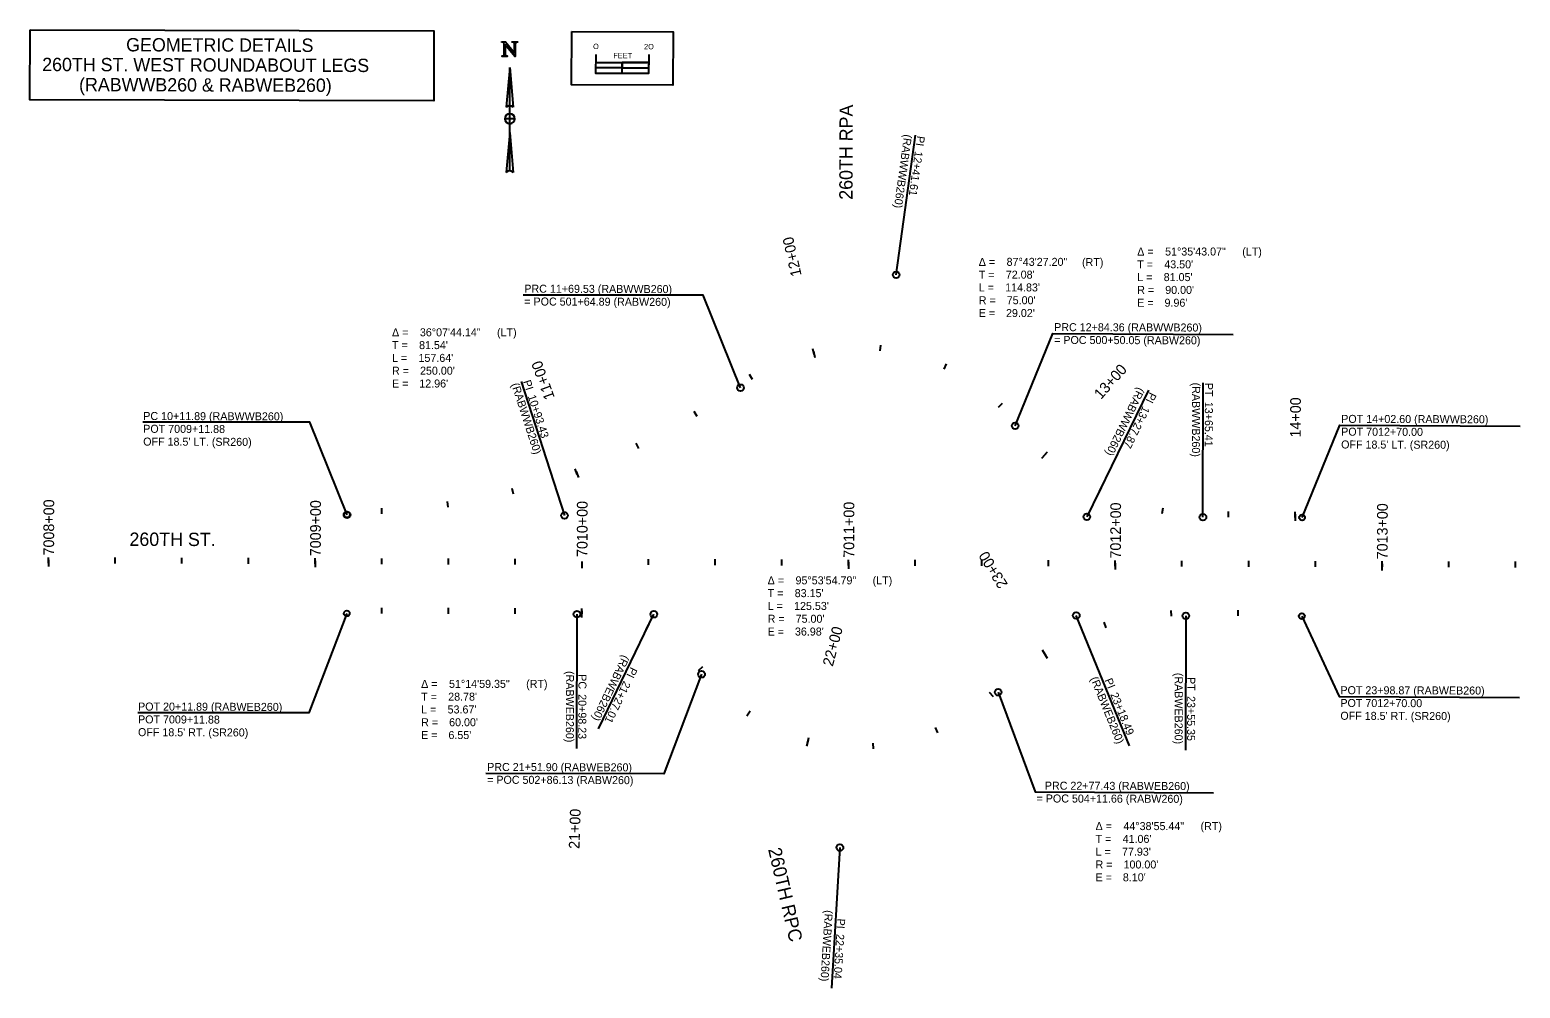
# Model space of a CAD drawing. Extents: x 5195296 to 5198948, y 3709168 to 3709552.
# Drawn here: x 5196591 to 5197150, y 3709193 to 3709552 of the extents above; entities that cross this region are included whole.
import ezdxf

# ---------------------------------------------------------------- set-up
doc = ezdxf.new("R2010")
doc.units = 0
for name, color, linetype in [('dsnAlignmentStation', 7, 'Continuous'), ('dsnGeopakCellProfile', 7, 'Continuous'), ('dsnProfileEntranceGradeProp', 7, 'Continuous')]:
    doc.layers.add(name, color=color, linetype=linetype)

msp = doc.modelspace()

# ---------------------------------------------------------------- linework, layer by layer
at = {"layer": 'dsnAlignmentStation'}
for p, q in [((5196597.84, 3709353.39), (5196597.83, 3709350.94)), ((5196622.84, 3709352.09), (5196622.84, 3709354.28)), ((5196647.84, 3709352.02), (5196647.84, 3709354.21)), ((5196672.84, 3709351.95), (5196672.84, 3709354.13)), ((5196697.84, 3709353.1), (5196697.83, 3709350.65)), ((5196722.84, 3709351.81), (5196722.84, 3709353.99)), ((5196747.84, 3709351.73), (5196747.84, 3709353.92)), ((5196772.84, 3709351.66), (5196772.84, 3709353.84)), ((5196822.84, 3709351.52), (5196822.84, 3709353.7)), ((5196847.84, 3709351.44), (5196847.84, 3709353.63)), ((5196872.84, 3709351.37), (5196872.84, 3709353.56)), ((5196922.84, 3709351.23), (5196922.84, 3709353.41)), ((5196947.84, 3709351.16), (5196947.84, 3709353.34)), ((5196972.84, 3709351.08), (5196972.84, 3709353.27)), ((5197022.84, 3709350.94), (5197022.84, 3709353.12)), ((5197047.84, 3709350.87), (5197047.84, 3709353.05)), ((5197072.84, 3709350.79), (5197072.84, 3709352.98)), ((5197122.84, 3709350.65), (5197122.84, 3709352.83)), ((5196797.84, 3709352.81), (5196797.83, 3709350.36)), ((5196897.84, 3709352.52), (5196897.83, 3709350.08)), ((5196997.84, 3709352.23), (5196997.83, 3709349.79)), ((5197097.84, 3709351.95), (5197097.83, 3709349.5)), ((5197147.84, 3709350.58), (5197147.84, 3709352.76))]:
    msp.add_line(p, q, dxfattribs=at)
at = {"layer": 'dsnGeopakCellProfile'}
for p, q in [((5196770.8, 3709538.11), (5196769.49, 3709523.16)), ((5196770.8, 3709538.11), (5196772.11, 3709523.16)), ((5196770.8, 3709523.73), (5196770.8, 3709538.11)), ((5196770.8, 3709499.27), (5196770.8, 3709538.11)), ((5196812.99, 3709535.93), (5196813, 3709539.93)), ((5196812.99, 3709535.93), (5196813, 3709539.93)), ((5196770.8, 3709523.7), (5196770.8, 3709523.73)), ((5196770.8, 3709518.86), (5196770.8, 3709520.73)), ((5196770.8, 3709518.86), (5196768.93, 3709518.86)), ((5196772.68, 3709518.86), (5196768.93, 3709518.86)), ((5196772.68, 3709518.86), (5196770.8, 3709518.86)), ((5196770.8, 3709516.98), (5196770.8, 3709518.86)), ((5196770.8, 3709513.68), (5196769.49, 3709498.74)), ((5196770.8, 3709499.27), (5196770.8, 3709513.68)), ((5196770.8, 3709513.68), (5196772.11, 3709498.74)), ((5196915.65, 3709460.32), (5196922.91, 3709512.62)), ((5196922.91, 3709512.62), (5196922.91, 3709512.62)), ((5196884.89, 3709430.46), (5196884.41, 3709432.59)), ((5196884.62, 3709431.65), (5196885.15, 3709429.26)), ((5196909.73, 3709431.82), (5196909.98, 3709433.99)), ((5196933.66, 3709424.98), (5196934.6, 3709426.95)), ((5196775.09, 3709420.35), (5196791.31, 3709370.11)), ((5196861.85, 3709421.04), (5196860.7, 3709422.9)), ((5197010.31, 3709417.01), (5196987.19, 3709369.54)), ((5197030.7, 3709369.42), (5197030.84, 3709419.82)), ((5197030.84, 3709419.82), (5197030.84, 3709419.82)), ((5196841.07, 3709407.15), (5196839.93, 3709409.01)), ((5196954.03, 3709410.68), (5196955.56, 3709412.24)), ((5196819.14, 3709395.18), (5196818.19, 3709397.15)), ((5196971.78, 3709393.24), (5196970.14, 3709391.42)), ((5196970.96, 3709392.33), (5196972.42, 3709393.96)), ((5196796.12, 3709385.46), (5196795.37, 3709387.51)), ((5196795.7, 3709386.61), (5196796.53, 3709384.31)), ((5196747.74, 3709373.13), (5196747.42, 3709375.29)), ((5196772.24, 3709378.09), (5196771.7, 3709380.2)), ((5196991.66, 3709378.45), (5196992.61, 3709380.41)), ((5196722.88, 3709370.65), (5196722.77, 3709372.83)), ((5197015.37, 3709370.78), (5197015.74, 3709372.93)), ((5197040.29, 3709369.39), (5197040.29, 3709371.57)), ((5197065.29, 3709370.54), (5197065.28, 3709368.09)), ((5197065.29, 3709369.32), (5197065.29, 3709371.5)), ((5196722.78, 3709333.31), (5196722.78, 3709335.49)), ((5196747.78, 3709333.23), (5196747.78, 3709335.42)), ((5196772.78, 3709333.16), (5196772.78, 3709335.35)), ((5196796, 3709333.09), (5196795.86, 3709282.69)), ((5196797.82, 3709334.29), (5196797.74, 3709331.84)), ((5196797.78, 3709333.06), (5196797.85, 3709335.25)), ((5196804.03, 3709290.06), (5196824.78, 3709333.01)), ((5197003.12, 3709283.65), (5196983.21, 3709332.55)), ((5196983.21, 3709332.55), (5196983.21, 3709332.55)), ((5197018.92, 3709332.31), (5197018.81, 3709334.49)), ((5197024.27, 3709332.43), (5197024.12, 3709282.03)), ((5197043.92, 3709332.38), (5197043.92, 3709334.56)), ((5196821.88, 3709327.14), (5196822.83, 3709329.11)), ((5196994.37, 3709327.95), (5196993.72, 3709330.04)), ((5196971.66, 3709317.65), (5196970.51, 3709319.51)), ((5196971.02, 3709318.7), (5196972.3, 3709316.61)), ((5196841.53, 3709311.98), (5196843.19, 3709313.39)), ((5196952.15, 3709302.11), (5196950.67, 3709303.72)), ((5196859.67, 3709294.94), (5196860.89, 3709296.76)), ((5196882.68, 3709285.92), (5196882.06, 3709283.55)), ((5196882.37, 3709284.73), (5196882.92, 3709286.85)), ((5196931.3, 3709288.53), (5196930.43, 3709290.53)), ((5196795.86, 3709282.69), (5196795.86, 3709282.69)), ((5196907.15, 3709282.51), (5196906.99, 3709284.69)), ((5196989.23, 3709267.82), (5196989.23, 3709267.82)), ((5196894.59, 3709245.52), (5196891.4, 3709192.82)), ((5196891.4, 3709192.82), (5196891.4, 3709192.82))]:
    msp.add_line(p, q, dxfattribs=at)
for points in [[(5196590.92, 3709552.19), (5196742.34, 3709551.75), (5196742.27, 3709525.5), (5196590.84, 3709525.93)], [(5196590.92, 3709552.19), (5196742.34, 3709551.75), (5196742.27, 3709525.5), (5196590.84, 3709525.93)], [(5196794.03, 3709551.58), (5196832.03, 3709551.47), (5196831.98, 3709531.47), (5196793.98, 3709531.58)], [(5196794.03, 3709551.58), (5196832.03, 3709551.47), (5196831.98, 3709531.47), (5196793.98, 3709531.58)], [(5196802.99, 3709535.95), (5196812.99, 3709535.93), (5196812.99, 3709537.94), (5196802.99, 3709537.97)], [(5196812.99, 3709537.94), (5196822.99, 3709537.91), (5196823, 3709539.9), (5196813, 3709539.93)]]:
    msp.add_lwpolyline(points, close=True, dxfattribs=at)
for points in [[(5196767.67, 3709547.72), (5196769.15, 3709547.72), (5196772.52, 3709543.59), (5196772.52, 3709546.77)], [(5196767.67, 3709547.57), (5196767.67, 3709547.72)], [(5196768.75, 3709543.17), (5196768.75, 3709547)], [(5196772.87, 3709546.77), (5196772.87, 3709542.13), (5196772.73, 3709542.13), (5196769.11, 3709546.56), (5196769.11, 3709543.17)], [(5196771.93, 3709547.57), (5196771.74, 3709547.57), (5196771.74, 3709547.72), (5196773.65, 3709547.72), (5196773.65, 3709547.57), (5196773.46, 3709547.57)], [(5196803.01, 3709542.95), (5196802.99, 3709535.95), (5196822.99, 3709535.9), (5196823.01, 3709542.9)], [(5196769.69, 3709542.37), (5196769.88, 3709542.37), (5196769.88, 3709542.22), (5196767.97, 3709542.22), (5196767.97, 3709542.37), (5196768.16, 3709542.37)], [(5196803, 3709539.95), (5196823, 3709539.9)], [(5196857.31, 3709417.99), (5196843.36, 3709452.68), (5196775.76, 3709452.74)], [(5196960.27, 3709403.71), (5196974.42, 3709438.32), (5197042.02, 3709437.98)], [(5196709.77, 3709370.34), (5196695.82, 3709405.03), (5196633.18, 3709405.08)], [(5197067.89, 3709369.31), (5197082.04, 3709403.92), (5197149.64, 3709403.58)], [(5196709.67, 3709333.34), (5196695.51, 3709296.08), (5196631.32, 3709296.13)], [(5197067.78, 3709332.31), (5197081.75, 3709302.18), (5197149.35, 3709301.85)], [(5196842.73, 3709310.51), (5196828.57, 3709273.25), (5196761.8, 3709273.3)], [(5196953.91, 3709303.78), (5196967.85, 3709266.44), (5197034.62, 3709266.1)]]:
    msp.add_lwpolyline(points, dxfattribs=at)
for centre, radius in [((5196915.65, 3709460.32), 1.25), ((5196857.31, 3709417.99), 1.25), ((5196857.31, 3709417.99), 1.25), ((5196960.27, 3709403.71), 1.25), ((5196960.27, 3709403.71), 1.25), ((5196709.77, 3709370.34), 1.25), ((5196709.77, 3709370.34), 1.07), ((5196791.31, 3709370.11), 1.25), ((5196987.19, 3709369.54), 1.25), ((5197030.7, 3709369.42), 1.25), ((5197067.89, 3709369.31), 1.07), ((5196709.67, 3709333.34), 1.07), ((5196796, 3709333.09), 1.25), ((5196824.78, 3709333.01), 1.25), ((5196983.21, 3709332.55), 1.25), ((5197024.27, 3709332.43), 1.25), ((5197067.78, 3709332.31), 1.07), ((5196842.73, 3709310.51), 1.25), ((5196842.73, 3709310.51), 1.25), ((5196953.91, 3709303.78), 1.25), ((5196953.91, 3709303.78), 1.25), ((5196894.59, 3709245.52), 1.25)]:
    msp.add_circle(centre, radius, dxfattribs=at)
for centre, start, end in [((5196770.8, 3709518.86), 90, 89.4464), ((5196770.8, 3709521.82), 45.7867, 134.2133), ((5196770.8, 3709521.82), 90, 134.2134), ((5196770.8, 3709518.86), 360, 89.9989), ((5196770.8, 3709518.86), 180, 270), ((5196770.8, 3709497.39), 45.7867, 134.2134), ((5196770.8, 3709497.39), 45.7867, 90)]:
    msp.add_arc(centre, 1.87, start, end, dxfattribs=at)
for points in [[(5196768.75, 3709547), (5196768.51, 3709547.28), (5196768.39, 3709547.37), (5196768.26, 3709547.46), (5196768.02, 3709547.54), (5196767.91, 3709547.57), (5196767.67, 3709547.57)], [(5196768.16, 3709542.37), (5196768.52, 3709542.37), (5196768.66, 3709542.58), (5196768.75, 3709542.71), (5196768.75, 3709543.17)], [(5196769.11, 3709543.17), (5196769.11, 3709542.67), (5196769.21, 3709542.54), (5196769.37, 3709542.37), (5196769.69, 3709542.37)], [(5196772.52, 3709546.77), (5196772.52, 3709547.28), (5196772.41, 3709547.4), (5196772.26, 3709547.57), (5196771.93, 3709547.57)], [(5196773.46, 3709547.57), (5196773.11, 3709547.57), (5196772.96, 3709547.36), (5196772.87, 3709547.23), (5196772.87, 3709546.77)]]:
    msp.add_open_spline(points, degree=3, dxfattribs=at)
at = {"layer": 'dsnProfileEntranceGradeProp'}
for p, q in [((5196597.84, 3709352.17), (5196597.84, 3709354.35)), ((5196697.84, 3709351.88), (5196697.84, 3709354.06)), ((5196897.84, 3709351.3), (5196897.84, 3709353.48)), ((5196997.84, 3709351.01), (5196997.84, 3709353.19)), ((5197097.84, 3709350.72), (5197097.84, 3709352.91)), ((5196797.84, 3709352.81), (5196797.83, 3709350.36))]:
    msp.add_line(p, q, dxfattribs=at)

# ---------------------------------------------------------------- texts
at = {"layer": 'dsnAlignmentStation'}
for s, p in [('7008+00', (5196599.93, 3709355.07)), ('7009+00', (5196699.93, 3709354.78)), ('7010+00', (5196799.93, 3709354.49)), ('7011+00', (5196899.93, 3709354.2)), ('7012+00', (5196999.93, 3709353.92)), ('7013+00', (5197099.93, 3709353.63))]:
    msp.add_text(s, height=4.008, rotation=89.8345, dxfattribs=at).set_placement(p)
at = {"layer": 'dsnGeopakCellProfile'}
for s, height, rotation, p in [('GEOMETRIC DETAILS', 5, 359.8345, (5196626.96, 3709544.1)), ('O', 2, 359.8345, (5196802.03, 3709544.96)), ('FEET', 2, 359.8345, (5196809.62, 3709541.54)), ('2O', 2, 359.8345, (5196821.14, 3709544.9)), ('260TH ST. WEST ROUNDABOUT LEGS', 5, 359.8345, (5196595.47, 3709536.7)), ('(RABWWB260 & RABWEB260)', 5, 359.8345, (5196609.3, 3709529.16)), ('260TH RPA', 5, 89.8345, (5196899.33, 3709488.45)), ('(RABWWB260)', 3, 262.1013, (5196918.66, 3709513.1)), ('PI ', 3, 262.1013, (5196923.51, 3709512.54)), ('12+41.61', 3, 262.1013, (5196922.71, 3709506.8)), ('12+00', 4.008, 102.6877, (5196880.25, 3709460.17)), ('PRC 11+69.53 (RABWWB260)', 3, 359.8345, (5196776.25, 3709453.62)), ('= POC 501+64.89 (RABW260)', 3, 359.8345, (5196776.24, 3709448.82)), ('PRC 12+84.36 (RABWWB260)', 3, 359.8345, (5196974.91, 3709439.2)), ('= POC 500+50.05 (RABW260)', 3, 359.8345, (5196974.9, 3709434.4)), ('11+00', 4.008, 110.0278, (5196787.72, 3709414.33)), ('13+00', 4.008, 48.194, (5196992.45, 3709413.36)), ('PI ', 3, 287.8989, (5196775.74, 3709420.32)), ('(RABWWB260)', 3, 287.8989, (5196771.35, 3709419.26)), ('10+93.43', 3, 287.8989, (5196777.52, 3709414.8)), ('(RABWWB260)', 3, 244.0368, (5197006.29, 3709418.35)), ('PI ', 3, 244.0368, (5197010.74, 3709416.52)), ('(RABWWB260)', 3, 269.8345, (5197026.66, 3709419.9)), ('PT', 3, 269.8345, (5197031.45, 3709419.81)), ('PC 10+11.89 (RABWWB260)', 3, 359.8345, (5196633.38, 3709405.88)), ('13+27.87', 3, 244.0368, (5197008.21, 3709411.31)), ('13+65.41', 3, 269.8345, (5197031.43, 3709412.7)), ('14+00', 4.008, 89.8345, (5197067.38, 3709399.31)), ('POT 7009+11.88 ', 3, 359.8345, (5196633.36, 3709401.08)), ('POT 14+02.60 (RABWWB260)', 3, 359.8345, (5197082.54, 3709404.8)), ("OFF 18.5' LT. (SR260)", 3, 359.8345, (5196633.35, 3709396.28)), ("OFF 18.5' LT. (SR260)", 3, 359.8345, (5197082.51, 3709395.2)), ('POT 7012+70.00', 3, 359.8345, (5197082.52, 3709400)), ('260TH ST.', 5, 359.8345, (5196628.2, 3709358.68)), ('23+00', 4.008, 121.5497, (5196957.67, 3709344.27)), ('22+00', 4.008, 75.3334, (5196891.9, 3709313.25)), ('(RABWEB260)', 3, 244.2095, (5196813.18, 3709317.98)), ('(RABWEB260)', 3, 269.8345, (5196791.89, 3709311.74)), ('PC', 3, 269.8345, (5196796.55, 3709310.55)), ('PI ', 3, 244.2095, (5196816.09, 3709313.48)), ('(RABWEB260)', 3, 292.1588, (5196988.41, 3709308.93)), ('PI ', 3, 292.1588, (5196993.73, 3709308.33)), ('(RABWEB260)', 3, 269.8345, (5197020.16, 3709311.08)), ('PT', 3, 269.8345, (5197024.81, 3709309.49)), ('20+98.23', 3, 269.8345, (5196796.52, 3709303.06)), ('21+27.01', 3, 244.2095, (5196813.56, 3709308.26)), ('23+18.49', 3, 292.1588, (5196995.91, 3709302.96)), ('POT 23+98.87 (RABWEB260)', 3, 359.8345, (5197082.24, 3709303.07)), ('POT 20+11.89 (RABWEB260)', 3, 359.8345, (5196631.43, 3709296.93)), ('23+55.35', 3, 269.8345, (5197024.79, 3709302.37)), ('POT 7012+70.00', 3, 359.8345, (5197082.23, 3709298.27)), ('POT 7009+11.88 ', 3, 359.8345, (5196631.42, 3709292.13)), ("OFF 18.5' RT. (SR260)", 3, 359.8345, (5197082.22, 3709293.47)), ("OFF 18.5' RT. (SR260)", 3, 359.8345, (5196631.41, 3709287.33)), ('PRC 21+51.90 (RABWEB260)', 3, 359.8345, (5196762.33, 3709274.28)), ('= POC 502+86.13 (RABW260)', 3, 359.8345, (5196762.31, 3709269.48)), ('PRC 22+77.43 (RABWEB260)', 3, 359.8345, (5196971.41, 3709267.26)), ('= POC 504+11.66 (RABW260)', 3, 359.8345, (5196968.31, 3709262.47)), ('21+00', 4.008, 88.1416, (5196796.92, 3709244.99)), ('260TH RPC', 5, 283.0965, (5196867.62, 3709244.93)), ('(RABWEB260)', 3, 266.5339, (5196888.92, 3709222.15)), ('PI ', 3, 266.5339, (5196893.59, 3709219)), ('22+35.04', 3, 266.5339, (5196893.24, 3709213.21))]:
    msp.add_text(s, height=height, rotation=rotation, dxfattribs=at).set_placement(p)
for s, p in [('Δ = ', (5197006.06, 3709467.55)), ('51°35\'43.07"', (5197016.51, 3709467.55)), (' (LT)', (5197044.31, 3709467.55)), ('Δ = ', (5196946.64, 3709463.68)), ('87°43\'27.20"', (5196957.08, 3709463.68)), (' (RT)', (5196984.25, 3709463.56)), ('T = ', (5197006.06, 3709462.75)), ("43.50'", (5197016.2, 3709462.75)), ('T = ', (5196946.64, 3709458.88)), ("72.08'", (5196956.78, 3709458.88)), ('L = ', (5197006.06, 3709457.95)), ("81.05'", (5197015.98, 3709457.95)), ('L = ', (5196946.64, 3709454.08)), ("114.83'", (5196956.55, 3709454.08)), ('R = ', (5197006.06, 3709453.15)), ("90.00'", (5197016.55, 3709453.15)), ('R = ', (5196946.64, 3709449.28)), ("75.00'", (5196957.13, 3709449.28)), ('E = ', (5197006.06, 3709448.35)), ("9.96'", (5197016.29, 3709448.35)), ('E = ', (5196946.64, 3709444.48)), ("29.02'", (5196956.86, 3709444.48)), ('Δ = ', (5196726.65, 3709437.26)), ('36°07\'44.14"', (5196737.1, 3709437.26)), (' (LT)', (5196764.9, 3709437.26)), ('T = ', (5196726.65, 3709432.46)), ("81.54'", (5196736.79, 3709432.46)), ('L = ', (5196726.65, 3709427.66)), ('R = ', (5196726.65, 3709422.86)), ("157.64'", (5196736.57, 3709427.66)), ("250.00'", (5196737.15, 3709422.86)), ('E = ', (5196726.65, 3709418.06)), ("12.96'", (5196736.88, 3709418.06)), ('Δ = ', (5196867.49, 3709344.25)), ('95°53\'54.79"', (5196877.94, 3709344.25)), (' (LT)', (5196905.73, 3709344.25)), ('T = ', (5196867.49, 3709339.45)), ("83.15'", (5196877.63, 3709339.45)), ('L = ', (5196867.49, 3709334.65)), ("125.53'", (5196877.4, 3709334.65)), ('R = ', (5196867.49, 3709329.85)), ("75.00'", (5196877.98, 3709329.85)), ('E = ', (5196867.49, 3709325.05)), ("36.98'", (5196877.72, 3709325.05)), ('Δ = ', (5196737.57, 3709305.44)), ('51°14\'59.35"', (5196748.02, 3709305.44)), (' (RT)', (5196775.82, 3709305.44)), ('T = ', (5196737.57, 3709300.64)), ("28.78'", (5196747.71, 3709300.64)), ('L = ', (5196737.57, 3709295.84)), ("53.67'", (5196747.49, 3709295.84)), ('R = ', (5196737.57, 3709291.04)), ("60.00'", (5196748.06, 3709291.04)), ('E = ', (5196737.57, 3709286.24)), ("6.55'", (5196747.8, 3709286.24)), ('Δ = ', (5196990.44, 3709252.1)), ('44°38\'55.44"', (5197000.88, 3709252.1)), (' (RT)', (5197028.68, 3709252.1)), ('T = ', (5196990.44, 3709247.3)), ("41.06'", (5197000.58, 3709247.3)), ('L = ', (5196990.44, 3709242.5)), ("77.93'", (5197000.35, 3709242.5)), ('R = ', (5196990.44, 3709237.7)), ('E = ', (5196990.44, 3709232.9)), ("8.10'", (5197000.67, 3709232.9)), ("100.00'", (5197000.93, 3709237.7))]:
    msp.add_text(s, height=3, dxfattribs=at).set_placement(p)
at = {"layer": 'dsnProfileEntranceGradeProp'}
msp.add_text('7010+00', height=4.008, rotation=89.8345, dxfattribs=at).set_placement((5196799.93, 3709354.49))

doc.saveas('drawing.dxf')
